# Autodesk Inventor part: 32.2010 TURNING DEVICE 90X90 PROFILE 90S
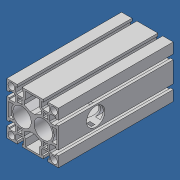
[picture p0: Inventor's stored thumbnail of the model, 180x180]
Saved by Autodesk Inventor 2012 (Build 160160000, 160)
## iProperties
Created: 2016-09
Part Number: 32.2010 TURNING DEVICE 90X90 PROFILE 90S
Material: Aluminum-6061
Description: PROFILE 90X90 S
Document SubType Name: Modeling
Designer: Admin
Stock Number: 20.1019 PROFILE 90X90 S
Density: 2.71 g/cm^3
Author: Admin
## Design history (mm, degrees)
sketch "Sketch1"
  geometry: L1 (-31.7, -15.7)-(-40.5, -15.7); L2 (-40.5, -15.7)-(-40.5, -18.25); L3 (-40.5, -18.25)-(-45, -18.25); L4 (-45, -18.25)-(-45, 18.25); L5 (-45, 18.25)-(-40.5, 18.25); L6 (-40.5, 18.25)-(-40.5, 15.7); L7 (-40.5, 15.7)-(-31.7, 15.7); L8 (-31.7, 15.7)-(-29.7, 17.7); L9 (-29.7, 17.7)-(-29.7, 27.3); L10 (-29.7, 27.3)-(-31.7, 29.3); L11 (-31.7, 29.3)-(-40.5, 29.3); L12 (-40.5, 29.3)-(-40.5, 26.75); L13 (-40.5, 26.75)-(-45, 26.75); L14 (-45, 26.75)-(-45, 45); L15 (29.3, 31.7)-(29.3, 40.5); L16 (-26.75, 45)-(-26.75, 40.5); L17 (-26.75, 40.5)-(-29.3, 40.5); L18 (-29.3, 40.5)-(-29.3, 31.7); L19 (-29.3, 31.7)-(-27.3, 29.7); L20 (-27.3, 29.7)-(-17.7, 29.7); L21 (-17.7, 29.7)-(-15.7, 31.7); L22 (-15.7, 31.7)-(-15.7, 40.5); L23 (-15.7, 40.5)-(-18.25, 40.5); L24 (-18.25, 40.5)-(-18.25, 45); L25 (-18.25, 45)-(18.25, 45); L26 (18.25, 45)-(18.25, 40.5); L27 (18.25, 40.5)-(15.7, 40.5); L28 (15.7, 40.5)-(15.7, 31.7); L29 (15.7, 31.7)-(17.7, 29.7); L30 (17.7, 29.7)-(27.3, 29.7); L31 (27.3, 29.7)-(29.3, 31.7); L32 (29.3, 40.5)-(26.75, 40.5); L33 (26.75, 40.5)-(26.75, 45); L34 (26.75, 45)-(45, 45); L35 (45, 45)-(45, 26.75); L36 (45, 26.75)-(40.5, 26.75); L37 (40.5, 26.75)-(40.5, 29.3); L38 (40.5, 29.3)-(31.7, 29.3); L39 (31.7, 29.3)-(29.7, 27.3); L40 (29.7, 27.3)-(29.7, 17.7); L41 (29.7, 17.7)-(31.7, 15.7); L42 (31.7, 15.7)-(40.5, 15.7); L43 (40.5, 15.7)-(40.5, 18.25); L44 (40.5, 18.25)-(45, 18.25); L45 (45, 18.25)-(45, -18.25); L46 (45, -18.25)-(40.5, -18.25); L47 (40.5, -18.25)-(40.5, -15.7); L48 (40.5, -15.7)-(31.7, -15.7); L49 (31.7, -15.7)-(29.7, -17.7); L50 (29.7, -17.7)-(29.7, -27.3); L51 (29.7, -27.3)-(31.7, -29.3); L52 (31.7, -29.3)-(40.5, -29.3); L53 (40.5, -29.3)-(40.5, -26.75); L54 (40.5, -26.75)-(45, -26.75); L55 (45, -26.75)-(45, -45); L56 (45, -45)-(26.75, -45); L57 (26.75, -45)-(26.75, -40.5); L58 (26.75, -40.5)-(29.3, -40.5); L59 (29.3, -40.5)-(29.3, -31.7); L60 (29.3, -31.7)-(27.3, -29.7); L61 (27.3, -29.7)-(17.7, -29.7); L62 (17.7, -29.7)-(15.7, -31.7); L63 (15.7, -31.7)-(15.7, -40.5); L64 (15.7, -40.5)-(18.25, -40.5)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; C1 r 5.85 at (37.15, 37.15); C2 r 5.85 at (-37.15, 37.15); C3 r 5.85 at (-37.15, -37.15); C4 r 5.85 at (37.15, -37.15); C5 r 16 at (18.5, 0); C6 r 16 at (-18.5, 0); A1 r 19 centre (18.5, 0) between (33.47, -11.7) and (33.47, 11.7); A2 r 19 centre (-18.5, 0) between (-33.47, 11.7) and (-33.47, -11.7); A3 r 3.75 centre (-22.5, 22.5) between (-24.16, 25.862) and (-24.348, 25.763); A4 r 3.75 centre (-22.5, 22.5) between (-20.651, 25.763) and (-24.16, 25.862); A5 r 3.75 centre (-22.5, 22.5) between (-19.137, 24.16) and (-19.237, 24.348); A6 r 3.75 centre (-22.5, 22.5) between (-19.137, 20.84) and (-19.137, 24.16); A7 r 3.75 centre (-22.5, 22.5) between (-19.237, 20.651) and (-19.137, 20.84); A8 r 3.75 centre (-22.5, 22.5) between (-24.16, 19.137) and (-20.651, 19.237); A9 r 3.75 centre (-22.5, 22.5) between (-24.348, 19.237) and (-24.16, 19.137); A10 r 3.75 centre (-22.5, 22.5) between (-25.763, 24.348) and (-25.763, 20.651); A11 r 3.75 centre (22.5, 22.5) between (20.84, 25.862) and (20.651, 25.763); A12 r 3.75 centre (22.5, 22.5) between (24.348, 25.763) and (20.84, 25.862); A13 r 3.75 centre (22.5, 22.5) between (25.862, 24.16) and (25.763, 24.348); A14 r 3.75 centre (22.5, 22.5) between (25.862, 20.84) and (25.862, 24.16); A15 r 3.75 centre (22.5, 22.5) between (25.763, 20.651) and (25.862, 20.84); A16 r 3.75 centre (22.5, 22.5) between (20.84, 19.137) and (24.348, 19.237); A17 r 3.75 centre (22.5, 22.5) between (20.651, 19.237) and (20.84, 19.137); A18 r 3.75 centre (22.5, 22.5) between (19.237, 24.348) and (19.237, 20.651); A19 r 3.75 centre (22.5, -22.5) between (20.84, -19.137) and (20.651, -19.237); A20 r 3.75 centre (22.5, -22.5) between (24.348, -19.237) and (20.84, -19.137); A21 r 3.75 centre (22.5, -22.5) between (25.862, -20.84) and (25.763, -20.651); A22 r 3.75 centre (22.5, -22.5) between (25.862, -24.16) and (25.862, -20.84); A23 r 3.75 centre (22.5, -22.5) between (25.763, -24.348) and (25.862, -24.16); A24 r 3.75 centre (22.5, -22.5) between (20.84, -25.862) and (24.348, -25.763); A25 r 3.75 centre (22.5, -22.5) between (20.651, -25.763) and (20.84, -25.862); A26 r 3.75 centre (22.5, -22.5) between (19.237, -20.651) and (19.237, -24.348); A27 r 3.75 centre (-22.5, -22.5) between (-24.16, -19.137) and (-24.348, -19.237); A28 r 3.75 centre (-22.5, -22.5) between (-20.651, -19.237) and (-24.16, -19.137); A29 r 3.75 centre (-22.5, -22.5) between (-19.137, -20.84) and (-19.237, -20.651); A30 r 3.75 centre (-22.5, -22.5) between (-19.137, -24.16) and (-19.137, -20.84); A31 r 3.75 centre (-22.5, -22.5) between (-19.237, -24.348) and (-19.137, -24.16); A32 r 3.75 centre (-22.5, -22.5) between (-24.16, -25.862) and (-20.651, -25.763); A33 r 3.75 centre (-22.5, -22.5) between (-24.348, -25.763) and (-24.16, -25.862); A34 r 3.75 centre (-22.5, -22.5) between (-25.763, -20.651) and (-25.763, -24.348)
  constraints: 322 end point, 68 point on circle, 40 centre point, 2 point on line
extrude "Extrusion2" new body sketch "Sketch1" distance "d2" = 200; taper "d3" = 0 deg
sketch "Sketch2"
  geometry: L1 (0, 36.5)-(0, 0) reference; C1 r 15.975 at (-65, 18.25); 2 further points
  constraints: 1 centre point, 1 horizontal alignment, 1 midpoint
  dimensions: "d4" = 31.95 diameter of C1; "d5" = 65 distance from line of C1.centre L1
extrude "Extrusion3" cut sketch "Sketch2" distance "d6" = 200; taper "d7" = 0 deg
body "Solid2"
